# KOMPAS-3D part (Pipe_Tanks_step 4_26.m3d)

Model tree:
1. X Axis
2. Y Axis
3. Z Axis  (labels: Bend 90 Dn 20; Pipe Dn 20)
     Òîëùèíà ñòåíêè 1 = 1

Referenced files in C:\Documents and Settings\kashirsky\Мои документы\Camtasia Studio\Pipelines3D\Tanks\: Tanks_step 4.a3d
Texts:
  Pipe Dn 20
  Steel ASTM A295
  Three Point Plane
  Plane at Angle
  Line and Point Plane
  Axis through Two Vertices
  Axis of Feature
  Axis of Conical Surface
  Axis through Edge
  Trim by Surface
  Trim by Sketch
  Feature with No History
  Intersection Axis of Two Planes
  Two Line Plane
  Line and Face Plane
  Bend by line
  Hole in sheet body
  Cut in sheet body
  Point in CM
  Linear Dimension from Line to Point
  Surface Finish Symbol
  Geometric Tolerance Symbol
  Leader #1
  Leader #2
  Leader #3
  Shape Deviations and Datum
  Node point number
  Mark of coordination axis
  Node point designation
  Mark/Reference designation with leader
  Mark/reference designation on line
  Mark/Reference designation without leader
  Bend 90 Dn 20
  Plane of section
